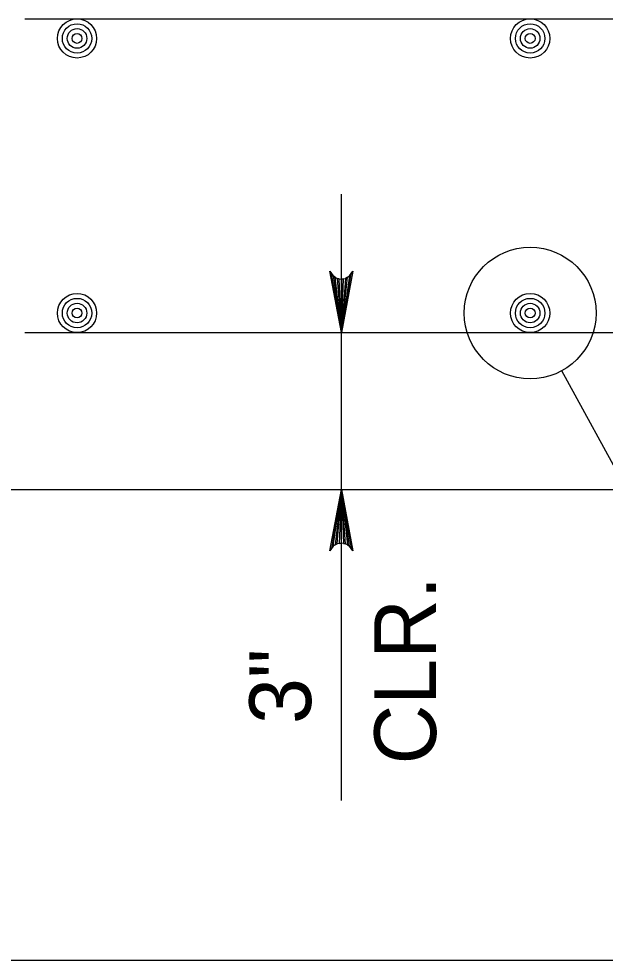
# Model space of a CAD drawing. Extents: x 638079 to 640019, y 297691 to 298879.
# Drawn here: x 639273.07 to 639301.56, y 298707.6 to 298753.32 of the extents above; entities that cross this region are included whole.
import ezdxf

# ---------------------------------------------------------------- set-up
doc = ezdxf.new("R2010")
doc.units = 0
doc.layers.add('1', color=7, linetype='Continuous')

msp = doc.modelspace()

# ---------------------------------------------------------------- linework, layer by layer
at = {"layer": '1'}
for p, q in [((639273.36, 298753.316), (639410.52, 298753.316)), ((639288.742, 298715.349), (639288.742, 298744.795)), ((639297.914, 298739.027), (639297.914, 298739.027)), ((639273.36, 298738.076), (639410.52, 298738.076)), ((639309.438, 298717.941), (639299.449, 298736.219)), ((639265.74, 298730.456), (639418.14, 298730.456)), ((639250.5, 298707.596), (639433.38, 298707.596))]:
    msp.add_line(p, q, dxfattribs=at)
for points in [[(639288.742, 298738.076), (639288.183, 298741.059), (639288.262, 298740.944), (639288.342, 298740.829), (639288.442, 298740.77), (639288.542, 298740.71), (639288.642, 298740.693), (639288.742, 298740.676), (639288.842, 298740.693), (639288.942, 298740.71), (639289.042, 298740.77), (639289.142, 298740.829), (639289.222, 298740.944), (639289.301, 298741.059), (639288.742, 298738.076), (639289.222, 298740.944), (639289.142, 298740.829), (639288.742, 298738.076), (639289.042, 298740.77), (639288.942, 298740.71), (639288.742, 298738.076), (639288.842, 298740.693), (639288.742, 298740.676), (639288.742, 298738.076), (639288.642, 298740.693), (639288.542, 298740.71), (639288.742, 298738.076), (639288.442, 298740.77), (639288.342, 298740.829), (639288.742, 298738.076), (639288.262, 298740.944)], [(639273.602, 298730.452), (639273.612, 298730.456)], [(639288.742, 298730.456), (639289.301, 298727.473), (639289.222, 298727.588), (639289.142, 298727.703), (639289.042, 298727.762), (639288.942, 298727.822), (639288.842, 298727.839), (639288.742, 298727.856), (639288.642, 298727.839), (639288.542, 298727.822), (639288.442, 298727.762), (639288.342, 298727.703), (639288.262, 298727.588), (639288.183, 298727.473), (639288.742, 298730.456), (639288.262, 298727.588), (639288.342, 298727.703), (639288.742, 298730.456), (639288.442, 298727.762), (639288.542, 298727.822), (639288.742, 298730.456), (639288.642, 298727.839), (639288.742, 298727.856), (639288.742, 298730.456), (639288.842, 298727.839), (639288.942, 298727.822), (639288.742, 298730.456), (639289.042, 298727.762), (639289.142, 298727.703), (639288.742, 298730.456), (639289.222, 298727.588)]]:
    msp.add_lwpolyline(points, dxfattribs=at)
for centre, radius in [((639275.899, 298752.365), 0.952), ((639275.899, 298752.365), 0.714), ((639297.914, 298752.365), 0.952), ((639297.914, 298752.365), 0.714), ((639275.899, 298752.365), 0.476), ((639275.899, 298752.365), 0.238), ((639297.914, 298752.365), 0.476), ((639297.914, 298752.365), 0.238), ((639297.914, 298739.027), 3.2), ((639275.899, 298739.027), 0.952), ((639275.899, 298739.027), 0.714), ((639297.914, 298739.027), 0.952), ((639297.914, 298739.027), 0.714), ((639275.899, 298739.027), 0.476), ((639275.899, 298739.027), 0.238), ((639297.914, 298739.027), 0.476), ((639297.914, 298739.027), 0.238)]:
    msp.add_circle(centre, radius, dxfattribs=at)

# ---------------------------------------------------------------- texts
for s, p in [('CLR.', (639293.341, 298717.106)), ('3"', (639287.269, 298719.066))]:
    msp.add_text(s, height=3, rotation=90, dxfattribs=at).set_placement(p)

doc.saveas('drawing.dxf')
